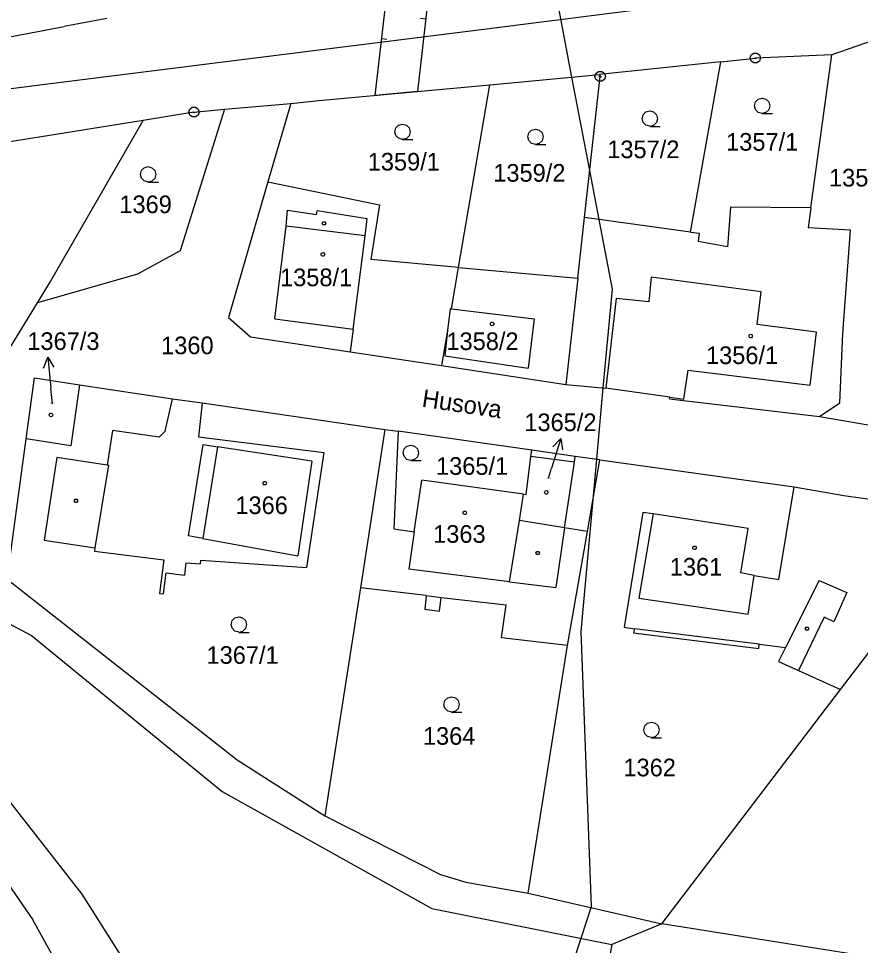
# Model space of a CAD drawing. Extents: x -806774 to -803680, y -1151731 to -1150053.
# Drawn here: x -804756.2 to -804675.1, y -1150604.7 to -1150515.4 of the extents above; entities that cross this region are included whole.
import ezdxf

# ---------------------------------------------------------------- set-up
doc = ezdxf.new("R2010")
doc.units = 0
for name, color, linetype in [('1', 7, 'Continuous'), ('11', 7, 'Continuous'), ('12', 7, 'Continuous'), ('13', 7, 'Continuous'), ('2', 7, 'Continuous'), ('3', 7, 'Continuous'), ('4', 7, 'Continuous'), ('5', 7, 'Continuous'), ('6', 7, 'Continuous'), ('7', 7, 'Continuous'), ('8', 7, 'Continuous')]:
    doc.layers.add(name, color=color, linetype=linetype)

msp = doc.modelspace()

# ---------------------------------------------------------------- linework, layer by layer
at = {"layer": '1'}
for p, q in [((-804747.72, -1150515.43), (-804751.83, -1150516.2)), ((-804763.49, -1150518.4), (-804751.83, -1150516.2)), ((-804671.85, -1150516.86), (-804677.85, -1150518.93)), ((-804688.56, -1150519.6), (-804700.23, -1150520.83)), ((-804691.48, -1150536.01), (-804688.56, -1150519.6)), ((-804688.56, -1150519.6), (-804685.22, -1150519.25)), ((-804677.85, -1150518.93), (-804685.22, -1150519.25)), ((-804679.88, -1150533.68), (-804677.85, -1150518.93)), ((-804710.79, -1150521.81), (-804700.23, -1150520.83)), ((-804701.68, -1150534.6), (-804700.17, -1150521.02)), ((-804700.23, -1150520.83), (-804700.17, -1150521.02)), ((-804727.28, -1150523.34), (-804710.79, -1150521.81)), ((-804713.82, -1150539.42), (-804710.79, -1150521.81)), ((-804736.36, -1150524.18), (-804740.64, -1150537.81)), ((-804739.31, -1150524.46), (-804736.36, -1150524.18)), ((-804736.36, -1150524.18), (-804729.97, -1150523.63)), ((-804729.97, -1150523.63), (-804732.19, -1150531.16)), ((-804729.97, -1150523.63), (-804727.28, -1150523.34)), ((-804739.31, -1150524.46), (-804744.2, -1150525.25)), ((-804744.2, -1150525.25), (-804766.8, -1150528.89)), ((-804753.24, -1150540.95), (-804744.2, -1150525.25)), ((-804732.19, -1150531.16), (-804735.99, -1150544.25)), ((-804732.19, -1150531.16), (-804721.42, -1150533.39)), ((-804721.42, -1150533.39), (-804722.26, -1150538.65)), ((-804687.61, -1150533.6), (-804687.89, -1150537.42)), ((-804679.88, -1150533.68), (-804687.61, -1150533.6)), ((-804679.88, -1150533.68), (-804680.14, -1150535.59)), ((-804702.34, -1150540.46), (-804701.68, -1150534.6)), ((-804691.48, -1150536.01), (-804701.68, -1150534.6)), ((-804676.04, -1150535.83), (-804680.14, -1150535.59)), ((-804691.48, -1150536.01), (-804690.63, -1150536.13)), ((-804690.63, -1150536.13), (-804690.74, -1150536.92)), ((-804676.8, -1150545.77), (-804676.04, -1150535.83)), ((-804687.89, -1150537.42), (-804690.74, -1150536.92)), ((-804740.64, -1150537.81), (-804744.74, -1150540.06)), ((-804713.82, -1150539.42), (-804722.26, -1150538.65)), ((-804744.74, -1150540.06), (-804754.4, -1150542.84)), ((-804714.51, -1150543.42), (-804713.82, -1150539.42)), ((-804713.82, -1150539.42), (-804702.34, -1150540.46)), ((-804754.4, -1150542.84), (-804753.24, -1150540.95)), ((-804702.34, -1150540.46), (-804703.48, -1150550.7)), ((-804758.67, -1150549.81), (-804754.4, -1150542.84)), ((-804714.64, -1150543.4), (-804714.87, -1150545.49)), ((-804714.51, -1150543.42), (-804714.64, -1150543.4)), ((-804735.99, -1150544.25), (-804733.85, -1150546.1)), ((-804714.87, -1150545.49), (-804715.46, -1150548.88)), ((-804733.85, -1150546.1), (-804724.25, -1150547.55)), ((-804677.08, -1150552.48), (-804676.8, -1150545.77)), ((-804724.25, -1150547.55), (-804715.46, -1150548.88)), ((-804715.46, -1150548.88), (-804703.48, -1150550.7)), ((-804755.47, -1150555.94), (-804754.67, -1150550.06)), ((-804754.67, -1150550.06), (-804750.33, -1150550.72)), ((-804750.33, -1150550.72), (-804751.16, -1150556.62)), ((-804750.33, -1150550.72), (-804741.39, -1150552.08)), ((-804703.48, -1150550.7), (-804699.63, -1150551.04)), ((-804693.47, -1150551.91), (-804699.63, -1150551.04)), ((-804742.08, -1150555.2), (-804741.39, -1150552.08)), ((-804741.39, -1150552.08), (-804738.53, -1150552.46)), ((-804738.53, -1150552.46), (-804738.89, -1150555.74)), ((-804738.53, -1150552.46), (-804720.91, -1150555.02)), ((-804693.49, -1150552.09), (-804693.47, -1150551.91)), ((-804693.49, -1150552.09), (-804679.04, -1150553.78)), ((-804679.04, -1150553.78), (-804677.08, -1150552.48)), ((-804679.04, -1150553.78), (-804671.44, -1150555.09)), ((-804747.16, -1150555.14), (-804747.69, -1150558.46)), ((-804742.68, -1150555.76), (-804747.16, -1150555.14)), ((-804742.68, -1150555.76), (-804742.08, -1150555.2)), ((-804720.91, -1150555.02), (-804723.28, -1150570.3)), ((-804720.91, -1150555.02), (-804719.65, -1150555.2)), ((-804719.65, -1150555.2), (-804720.05, -1150564.62)), ((-804706.77, -1150557.03), (-804719.65, -1150555.2)), ((-804757.3, -1150569.44), (-804755.47, -1150555.94)), ((-804751.16, -1150556.62), (-804755.47, -1150555.94)), ((-804738.89, -1150555.74), (-804726.81, -1150557.24)), ((-804726.81, -1150557.24), (-804728.47, -1150568.34)), ((-804706.85, -1150557.64), (-804706.77, -1150557.03)), ((-804702.57, -1150557.62), (-804706.77, -1150557.03)), ((-804752.52, -1150557.74), (-804753.73, -1150565.68)), ((-804747.69, -1150558.46), (-804752.52, -1150557.74)), ((-804707.32, -1150561.31), (-804706.85, -1150557.64)), ((-804700.2, -1150557.94), (-804702.57, -1150557.62)), ((-804701.41, -1150564.85), (-804700.2, -1150557.94)), ((-804700.2, -1150557.94), (-804681.49, -1150560.57)), ((-804718.08, -1150564.9), (-804717.35, -1150559.9)), ((-804707.55, -1150561.25), (-804717.35, -1150559.9)), ((-804682.97, -1150569.49), (-804681.49, -1150560.57)), ((-804681.49, -1150560.57), (-804676.7, -1150561.39)), ((-804707.95, -1150563.81), (-804707.55, -1150561.25)), ((-804707.55, -1150561.25), (-804707.32, -1150561.31)), ((-804676.7, -1150561.39), (-804670.97, -1150562.21)), ((-804696.05, -1150563.02), (-804697.86, -1150574.08)), ((-804695.06, -1150563.17), (-804696.05, -1150563.02)), ((-804685.91, -1150564.57), (-804695.06, -1150563.17)), ((-804703.6, -1150564.5), (-804707.95, -1150563.81)), ((-804720.05, -1150564.62), (-804718.08, -1150564.9)), ((-804701.41, -1150564.85), (-804703.6, -1150564.5)), ((-804703.33, -1150575.86), (-804701.41, -1150564.85)), ((-804686.63, -1150568.85), (-804685.91, -1150564.57)), ((-804753.73, -1150565.68), (-804748.85, -1150566.42)), ((-804748.85, -1150566.42), (-804748.89, -1150566.77)), ((-804748.89, -1150566.77), (-804742.21, -1150567.6)), ((-804742.21, -1150567.6), (-804742.62, -1150570.83)), ((-804740.08, -1150567.87), (-804740.23, -1150569.07)), ((-804740.08, -1150567.87), (-804738.67, -1150567.97)), ((-804738.67, -1150567.97), (-804738.65, -1150567.62)), ((-804738.65, -1150567.62), (-804728.47, -1150568.34)), ((-804742.25, -1150570.88), (-804742, -1150568.85)), ((-804742, -1150568.85), (-804740.23, -1150569.07)), ((-804685.35, -1150569.09), (-804686.63, -1150568.85)), ((-804765.48, -1150569.34), (-804754.97, -1150574.87)), ((-804757.3, -1150569.44), (-804735.14, -1150586.85)), ((-804685.35, -1150569.09), (-804682.97, -1150569.49)), ((-804723.28, -1150570.3), (-804726.69, -1150592.24)), ((-804716.93, -1150571.04), (-804723.28, -1150570.3)), ((-804742.62, -1150570.83), (-804742.25, -1150570.88)), ((-804716.93, -1150571.04), (-804717.08, -1150572.33)), ((-804715.65, -1150572.54), (-804715.49, -1150571.21)), ((-804715.49, -1150571.21), (-804709.22, -1150571.94)), ((-804677.01, -1150580.07), (-804670.08, -1150570.98)), ((-804717.08, -1150572.33), (-804715.65, -1150572.54)), ((-804709.68, -1150575.1), (-804709.22, -1150571.94)), ((-804697.86, -1150574.08), (-804696.86, -1150574.23)), ((-804754.97, -1150574.87), (-804736.59, -1150589.91)), ((-804703.33, -1150575.86), (-804709.68, -1150575.1)), ((-804696.86, -1150574.23), (-804696.95, -1150574.63)), ((-804696.95, -1150574.63), (-804684.89, -1150576.12)), ((-804707.1, -1150599.7), (-804703.33, -1150575.86)), ((-804684.89, -1150576.12), (-804684.84, -1150575.72)), ((-804684.84, -1150575.72), (-804682.31, -1150576.03)), ((-804768.67, -1150576.05), (-804750.12, -1150599.8)), ((-804682.31, -1150576.03), (-804682.98, -1150577.37)), ((-804682.98, -1150577.37), (-804681.05, -1150578.24)), ((-804681.05, -1150578.24), (-804677.01, -1150580.07)), ((-804694.22, -1150602.66), (-804677.01, -1150580.07)), ((-804768.67, -1150582.3), (-804754.83, -1150602.27)), ((-804735.14, -1150586.85), (-804726.69, -1150592.24)), ((-804736.59, -1150589.91), (-804716.38, -1150601.17)), ((-804726.69, -1150592.24), (-804715.56, -1150597.91)), ((-804715.56, -1150597.91), (-804713.12, -1150598.64)), ((-804713.12, -1150598.64), (-804707.1, -1150599.7)), ((-804750.12, -1150599.8), (-804728.74, -1150633.39)), ((-804707.1, -1150599.7), (-804694.22, -1150602.66)), ((-804716.38, -1150601.17), (-804699.05, -1150604.64)), ((-804739.17, -1150630.73), (-804754.83, -1150602.27)), ((-804694.22, -1150602.66), (-804699.05, -1150604.64)), ((-804653.81, -1150609.12), (-804694.22, -1150602.66)), ((-804699.05, -1150604.64), (-804701.95, -1150620.52))]:
    msp.add_line(p, q, dxfattribs=at)
at = {"layer": '11'}
msp.add_lwpolyline([(-804712.5, -1150636), (-804702, -1150604.05), (-804701.03, -1150601.09), (-804701, -1150601), (-804702, -1150574.5), (-804700.81, -1150561.44), (-804700.49, -1150557.9), (-804699.87, -1150551.02), (-804699, -1150541.5), (-804700.28, -1150534.79), (-804701.18, -1150530.07), (-804702.89, -1150521.08), (-804705.23, -1150508.8), (-804707.48, -1150497), (-804708.64, -1150490.89), (-804709.2, -1150487.94), (-804711, -1150478.5), (-804713.95, -1150471.68), (-804723.17, -1150450.35)], dxfattribs=at)
at = {"layer": '12'}
for p, q in [((-804731.53, -1150544.37), (-804730.44, -1150535.43)), ((-804722.82, -1150536.38), (-804730.44, -1150535.43)), ((-804723.97, -1150545.37), (-804722.82, -1150536.38)), ((-804695.25, -1150540.37), (-804695.49, -1150542.73)), ((-804684.65, -1150541.76), (-804695.25, -1150540.37)), ((-804685.06, -1150544.92), (-804684.65, -1150541.76)), ((-804698.62, -1150542.42), (-804699.63, -1150551.04)), ((-804695.49, -1150542.73), (-804698.62, -1150542.42)), ((-804714.64, -1150543.4), (-804714.87, -1150545.49)), ((-804714.51, -1150543.42), (-804714.64, -1150543.4)), ((-804714.51, -1150543.42), (-804706.54, -1150544.38)), ((-804731.53, -1150544.37), (-804723.97, -1150545.37)), ((-804706.54, -1150544.38), (-804707.12, -1150549.13)), ((-804714.87, -1150545.49), (-804715.14, -1150547.92)), ((-804679.32, -1150545.66), (-804685.06, -1150544.92)), ((-804679.93, -1150550.77), (-804679.32, -1150545.66)), ((-804715.14, -1150547.92), (-804707.12, -1150549.13)), ((-804755.47, -1150555.94), (-804754.67, -1150550.06)), ((-804754.67, -1150550.06), (-804750.33, -1150550.72)), ((-804692.11, -1150552.1), (-804691.71, -1150549.33)), ((-804691.71, -1150549.33), (-804679.93, -1150550.77)), ((-804750.33, -1150550.72), (-804751.16, -1150556.62)), ((-804693.47, -1150551.91), (-804699.63, -1150551.04)), ((-804693.47, -1150551.91), (-804692.11, -1150552.1)), ((-804751.16, -1150556.62), (-804755.47, -1150555.94)), ((-804737.03, -1150556.7), (-804738.47, -1150565.53)), ((-804727.95, -1150558.1), (-804737.03, -1150556.7)), ((-804727.95, -1150558.1), (-804729.3, -1150567.19)), ((-804707.32, -1150561.31), (-804706.85, -1150557.64)), ((-804702.65, -1150558.17), (-804706.85, -1150557.64)), ((-804703.6, -1150564.5), (-804702.65, -1150558.17)), ((-804718.08, -1150564.9), (-804717.35, -1150559.9)), ((-804707.55, -1150561.25), (-804717.35, -1150559.9)), ((-804707.95, -1150563.81), (-804707.55, -1150561.25)), ((-804707.95, -1150563.81), (-804707.55, -1150561.25)), ((-804707.55, -1150561.25), (-804707.32, -1150561.31)), ((-804695.06, -1150563.17), (-804696.44, -1150571.27)), ((-804685.91, -1150564.57), (-804695.06, -1150563.17)), ((-804708.9, -1150569.7), (-804707.95, -1150563.81)), ((-804703.6, -1150564.5), (-804707.95, -1150563.81)), ((-804718.08, -1150564.9), (-804718.6, -1150568.49)), ((-804686.63, -1150568.85), (-804685.91, -1150564.57)), ((-804738.47, -1150565.53), (-804729.3, -1150567.19)), ((-804708.9, -1150569.7), (-804718.6, -1150568.49)), ((-804685.35, -1150569.09), (-804686.63, -1150568.85)), ((-804685.91, -1150572.82), (-804685.35, -1150569.09)), ((-804696.44, -1150571.27), (-804685.91, -1150572.82))]:
    msp.add_line(p, q, dxfattribs=at)
at = {"layer": '13'}
for p, q in [((-804721.84, -1150522.84), (-804720.43, -1150510.49)), ((-804716.36, -1150510.04), (-804717.79, -1150522.46)), ((-804716.989, -1150515.504), (-804717.486, -1150515.447)), ((-804721.216, -1150517.375), (-804720.719, -1150517.432)), ((-804717.79, -1150522.46), (-804721.84, -1150522.84))]:
    msp.add_line(p, q, dxfattribs=at)
at = {"layer": '3'}
for points in [[(-804684.56, -1150524.58), (-804684.94, -1150524.48), (-804685.21, -1150524.21), (-804685.31, -1150523.84), (-804685.21, -1150523.47), (-804684.94, -1150523.2), (-804684.57, -1150523.1), (-804684.2, -1150523.2), (-804683.93, -1150523.47), (-804683.83, -1150523.85), (-804683.93, -1150524.23), (-804684.2, -1150524.5), (-804684.58, -1150524.6), (-804683.58, -1150524.6)], [(-804695.38, -1150525.82), (-804695.76, -1150525.72), (-804696.03, -1150525.45), (-804696.13, -1150525.08), (-804696.03, -1150524.71), (-804695.76, -1150524.44), (-804695.39, -1150524.34), (-804695.02, -1150524.44), (-804694.75, -1150524.71), (-804694.65, -1150525.09), (-804694.75, -1150525.47), (-804695.02, -1150525.74), (-804695.4, -1150525.84), (-804694.4, -1150525.84)], [(-804719.21, -1150527.08), (-804719.59, -1150526.98), (-804719.86, -1150526.71), (-804719.96, -1150526.34), (-804719.86, -1150525.97), (-804719.59, -1150525.7), (-804719.22, -1150525.6), (-804718.85, -1150525.7), (-804718.58, -1150525.97), (-804718.48, -1150526.35), (-804718.58, -1150526.73), (-804718.85, -1150527), (-804719.23, -1150527.1), (-804718.23, -1150527.1)], [(-804706.4, -1150527.57), (-804706.78, -1150527.47), (-804707.05, -1150527.2), (-804707.15, -1150526.83), (-804707.05, -1150526.46), (-804706.78, -1150526.19), (-804706.41, -1150526.09), (-804706.04, -1150526.19), (-804705.77, -1150526.46), (-804705.67, -1150526.84), (-804705.77, -1150527.22), (-804706.04, -1150527.49), (-804706.42, -1150527.59), (-804705.42, -1150527.59)], [(-804743.72, -1150531.19), (-804744.1, -1150531.09), (-804744.37, -1150530.82), (-804744.47, -1150530.45), (-804744.37, -1150530.08), (-804744.1, -1150529.81), (-804743.73, -1150529.71), (-804743.36, -1150529.81), (-804743.09, -1150530.08), (-804742.99, -1150530.46), (-804743.09, -1150530.84), (-804743.36, -1150531.11), (-804743.74, -1150531.21), (-804742.74, -1150531.21)], [(-804718.41, -1150558.01), (-804718.79, -1150557.91), (-804719.06, -1150557.64), (-804719.16, -1150557.27), (-804719.06, -1150556.9), (-804718.79, -1150556.63), (-804718.42, -1150556.53), (-804718.05, -1150556.63), (-804717.78, -1150556.9), (-804717.68, -1150557.28), (-804717.78, -1150557.66), (-804718.05, -1150557.93), (-804718.43, -1150558.03), (-804717.43, -1150558.03)], [(-804734.98, -1150574.56), (-804735.36, -1150574.46), (-804735.63, -1150574.19), (-804735.73, -1150573.82), (-804735.63, -1150573.45), (-804735.36, -1150573.18), (-804734.99, -1150573.08), (-804734.62, -1150573.18), (-804734.35, -1150573.45), (-804734.25, -1150573.83), (-804734.35, -1150574.21), (-804734.62, -1150574.48), (-804735, -1150574.58), (-804734, -1150574.58)], [(-804714.48, -1150582.26), (-804714.86, -1150582.16), (-804715.13, -1150581.89), (-804715.23, -1150581.52), (-804715.13, -1150581.15), (-804714.86, -1150580.88), (-804714.49, -1150580.78), (-804714.12, -1150580.88), (-804713.85, -1150581.15), (-804713.75, -1150581.53), (-804713.85, -1150581.91), (-804714.12, -1150582.18), (-804714.5, -1150582.28), (-804713.5, -1150582.28)], [(-804695.23, -1150584.71), (-804695.61, -1150584.61), (-804695.88, -1150584.34), (-804695.98, -1150583.97), (-804695.88, -1150583.6), (-804695.61, -1150583.33), (-804695.24, -1150583.23), (-804694.87, -1150583.33), (-804694.6, -1150583.6), (-804694.5, -1150583.98), (-804694.6, -1150584.36), (-804694.87, -1150584.63), (-804695.25, -1150584.73), (-804694.25, -1150584.73)]]:
    msp.add_lwpolyline(points, dxfattribs=at)
at = {"layer": '4'}
for p, q in [((-804730.44, -1150535.43), (-804730.29, -1150533.9)), ((-804730.29, -1150533.9), (-804727.51, -1150534.31)), ((-804727.51, -1150534.31), (-804727.44, -1150533.95)), ((-804722.63, -1150534.73), (-804727.44, -1150533.95)), ((-804722.82, -1150536.38), (-804722.63, -1150534.73)), ((-804731.53, -1150544.37), (-804730.44, -1150535.43)), ((-804722.82, -1150536.38), (-804730.44, -1150535.43)), ((-804723.97, -1150545.37), (-804722.82, -1150536.38)), ((-804695.25, -1150540.37), (-804695.49, -1150542.73)), ((-804684.65, -1150541.76), (-804695.25, -1150540.37)), ((-804685.06, -1150544.92), (-804684.65, -1150541.76)), ((-804698.62, -1150542.42), (-804699.63, -1150551.04)), ((-804695.49, -1150542.73), (-804698.62, -1150542.42)), ((-804714.51, -1150543.42), (-804706.54, -1150544.38)), ((-804731.53, -1150544.37), (-804723.97, -1150545.37)), ((-804706.54, -1150544.38), (-804707.12, -1150549.13)), ((-804723.97, -1150545.37), (-804724.25, -1150547.55)), ((-804714.87, -1150545.49), (-804715.14, -1150547.92)), ((-804679.32, -1150545.66), (-804685.06, -1150544.92)), ((-804679.93, -1150550.77), (-804679.32, -1150545.66)), ((-804715.14, -1150547.92), (-804707.12, -1150549.13)), ((-804692.11, -1150552.1), (-804691.71, -1150549.33)), ((-804691.71, -1150549.33), (-804679.93, -1150550.77)), ((-804693.47, -1150551.91), (-804692.11, -1150552.1)), ((-804739.85, -1150565.28), (-804738.41, -1150556.49)), ((-804737.03, -1150556.7), (-804738.47, -1150565.53)), ((-804738.41, -1150556.49), (-804737.03, -1150556.7)), ((-804727.95, -1150558.1), (-804737.03, -1150556.7)), ((-804727.95, -1150558.1), (-804729.3, -1150567.19)), ((-804702.65, -1150558.17), (-804706.85, -1150557.64)), ((-804702.65, -1150558.17), (-804702.57, -1150557.62)), ((-804747.55, -1150558.47), (-804748.85, -1150566.42)), ((-804747.55, -1150558.47), (-804747.69, -1150558.46)), ((-804703.6, -1150564.5), (-804702.65, -1150558.17)), ((-804695.06, -1150563.17), (-804696.44, -1150571.27)), ((-804708.9, -1150569.7), (-804707.95, -1150563.81)), ((-804738.47, -1150565.53), (-804739.85, -1150565.28)), ((-804718.08, -1150564.9), (-804718.6, -1150568.49)), ((-804703.6, -1150564.5), (-804704.45, -1150570.25)), ((-804738.47, -1150565.53), (-804729.3, -1150567.19)), ((-804708.9, -1150569.7), (-804718.6, -1150568.49)), ((-804708.9, -1150569.7), (-804704.45, -1150570.25)), ((-804685.91, -1150572.82), (-804685.35, -1150569.09)), ((-804679.08, -1150569.57), (-804682.31, -1150576.03)), ((-804679.08, -1150569.57), (-804676.4, -1150570.73)), ((-804716.93, -1150571.04), (-804715.49, -1150571.21)), ((-804696.44, -1150571.27), (-804685.91, -1150572.82)), ((-804676.4, -1150570.73), (-804677.65, -1150573.57)), ((-804678.6, -1150573.12), (-804681.05, -1150578.24)), ((-804677.65, -1150573.57), (-804678.6, -1150573.12)), ((-804684.84, -1150575.72), (-804696.86, -1150574.23))]:
    msp.add_line(p, q, dxfattribs=at)
at = {"layer": '5'}
for points in [[(-804726.7, -1150535.02), (-804726.61, -1150535.17), (-804726.7, -1150535.32), (-804726.88, -1150535.32), (-804726.97, -1150535.17), (-804726.88, -1150535.02)], [(-804726.9, -1150537.99), (-804726.8, -1150538.01), (-804726.75, -1150538.1), (-804726.73, -1150538.16), (-804726.75, -1150538.25), (-804726.83, -1150538.32), (-804726.9, -1150538.33), (-804726.99, -1150538.3), (-804727.05, -1150538.24), (-804727.07, -1150538.16), (-804727.05, -1150538.07), (-804726.97, -1150538)], [(-804710.58, -1150544.69), (-804710.48, -1150544.71), (-804710.43, -1150544.8), (-804710.41, -1150544.86), (-804710.43, -1150544.95), (-804710.51, -1150545.02), (-804710.58, -1150545.03), (-804710.67, -1150545), (-804710.73, -1150544.94), (-804710.75, -1150544.86), (-804710.73, -1150544.77), (-804710.65, -1150544.7)], [(-804685.67, -1150545.86), (-804685.57, -1150545.88), (-804685.52, -1150545.97), (-804685.5, -1150546.03), (-804685.52, -1150546.12), (-804685.6, -1150546.19), (-804685.67, -1150546.2), (-804685.76, -1150546.17), (-804685.82, -1150546.11), (-804685.84, -1150546.03), (-804685.82, -1150545.94), (-804685.74, -1150545.87)], [(-804753.09, -1150553.46), (-804752.99, -1150553.48), (-804752.94, -1150553.57), (-804752.92, -1150553.63), (-804752.94, -1150553.72), (-804753.02, -1150553.79), (-804753.09, -1150553.8), (-804753.18, -1150553.77), (-804753.24, -1150553.71), (-804753.26, -1150553.63), (-804753.24, -1150553.54), (-804753.16, -1150553.47)], [(-804732.49, -1150560.04), (-804732.39, -1150560.06), (-804732.34, -1150560.15), (-804732.32, -1150560.21), (-804732.34, -1150560.3), (-804732.42, -1150560.37), (-804732.49, -1150560.38), (-804732.58, -1150560.35), (-804732.64, -1150560.29), (-804732.66, -1150560.21), (-804732.64, -1150560.12), (-804732.56, -1150560.05)], [(-804705.37, -1150560.92), (-804705.27, -1150560.94), (-804705.22, -1150561.03), (-804705.2, -1150561.09), (-804705.22, -1150561.18), (-804705.3, -1150561.25), (-804705.37, -1150561.26), (-804705.46, -1150561.23), (-804705.52, -1150561.17), (-804705.54, -1150561.09), (-804705.52, -1150561), (-804705.44, -1150560.93)], [(-804750.59, -1150561.76), (-804750.5, -1150561.91), (-804750.59, -1150562.06), (-804750.77, -1150562.06), (-804750.86, -1150561.91), (-804750.77, -1150561.76)], [(-804713.22, -1150562.89), (-804713.12, -1150562.91), (-804713.07, -1150563), (-804713.05, -1150563.06), (-804713.07, -1150563.15), (-804713.15, -1150563.22), (-804713.22, -1150563.23), (-804713.31, -1150563.2), (-804713.37, -1150563.14), (-804713.39, -1150563.06), (-804713.37, -1150562.97), (-804713.29, -1150562.9)], [(-804706.1, -1150566.79), (-804706.01, -1150566.94), (-804706.1, -1150567.09), (-804706.28, -1150567.09), (-804706.37, -1150566.94), (-804706.28, -1150566.79)], [(-804691.09, -1150566.26), (-804690.99, -1150566.28), (-804690.94, -1150566.37), (-804690.92, -1150566.43), (-804690.94, -1150566.52), (-804691.02, -1150566.59), (-804691.09, -1150566.6), (-804691.18, -1150566.57), (-804691.24, -1150566.51), (-804691.26, -1150566.43), (-804691.24, -1150566.34), (-804691.16, -1150566.27)], [(-804680.16, -1150574.07), (-804680.07, -1150574.22), (-804680.16, -1150574.37), (-804680.34, -1150574.37), (-804680.43, -1150574.22), (-804680.34, -1150574.07)]]:
    msp.add_lwpolyline(points, close=True, dxfattribs=at)
at = {"layer": '6'}
for p, q in [((-804711.9, -1150516.53), (-804689.85, -1150513.74)), ((-804745.47, -1150520.74), (-804711.9, -1150516.53)), ((-804770.86, -1150523.92), (-804745.47, -1150520.74))]:
    msp.add_line(p, q, dxfattribs=at)
at = {"layer": '7'}
for p, q in [((-804753.394, -1150548.074), (-804753.1, -1150551.06)), ((-804752.95, -1150552.55), (-804753.1, -1150551.06)), ((-804703.974, -1150555.901), (-804704.85, -1150558.77)), ((-804705.14, -1150559.73), (-804704.85, -1150558.77))]:
    msp.add_line(p, q, dxfattribs=at)
for points in [[(-804753.793, -1150549.119), (-804753.394, -1150548.074), (-804752.798, -1150549.021)], [(-804704.744, -1150556.711), (-804703.974, -1150555.901), (-804703.788, -1150557.003)]]:
    msp.add_lwpolyline(points, dxfattribs=at)
at = {"layer": '8'}
for p, q in [((-804685.34, -1150519.25), (-804685.1, -1150519.25)), ((-804700.29, -1150521.02), (-804700.05, -1150521.02)), ((-804739.43, -1150524.46), (-804739.19, -1150524.46))]:
    msp.add_line(p, q, dxfattribs=at)
for points in [[(-804685.07, -1150518.77), (-804684.82, -1150518.95), (-804684.72, -1150519.24), (-804684.82, -1150519.53), (-804685.07, -1150519.71), (-804685.38, -1150519.71), (-804685.63, -1150519.53), (-804685.73, -1150519.24), (-804685.63, -1150518.95), (-804685.38, -1150518.77)], [(-804700.02, -1150520.54), (-804699.77, -1150520.72), (-804699.67, -1150521.01), (-804699.77, -1150521.3), (-804700.02, -1150521.48), (-804700.33, -1150521.48), (-804700.58, -1150521.3), (-804700.68, -1150521.01), (-804700.58, -1150520.72), (-804700.33, -1150520.54)], [(-804739.16, -1150523.98), (-804738.91, -1150524.16), (-804738.81, -1150524.45), (-804738.91, -1150524.74), (-804739.16, -1150524.92), (-804739.47, -1150524.92), (-804739.72, -1150524.74), (-804739.82, -1150524.45), (-804739.72, -1150524.16), (-804739.47, -1150523.98)]]:
    msp.add_lwpolyline(points, close=True, dxfattribs=at)

# ---------------------------------------------------------------- texts
at = {"layer": '2'}
for s, height, p in [('1357/1', 1.7, (-804688.04, -1150528.17)), ('1357/2', 1.7, (-804699.492, -1150528.89)), ('1359/1', 1.7, (-804722.57, -1150530.08)), ('1359/2', 1.7, (-804710.472, -1150531.16)), ('1355', 1.7, (-804678.126, -1150531.62)), ('1369', 1.7, (-804746.502, -1150534.19)), ('1358/1', 1.7, (-804731.017, -1150541.23)), ('1358/2', 1.7, (-804714.989, -1150547.38)), ('1360', 1.7, (-804742.479, -1150547.78)), ('1356/1', 1.7, (-804689.98, -1150548.73)), ('1367/3', 0.1, (-804753.18, -1150552.55)), ('1365/1', 1.7, (-804715.99, -1150559.4)), ('1365/2', 0.1, (-804705.374, -1150559.73)), ('1366', 1.7, (-804735.322, -1150563.18)), ('1363', 1.7, (-804716.269, -1150565.95)), ('1361', 1.7, (-804693.464, -1150569.11)), ('1367/1', 1.7, (-804738.103, -1150577.61)), ('1364', 1.7, (-804717.252, -1150585.41)), ('1362', 1.7, (-804697.936, -1150588.45))]:
    msp.add_text(s, height=height, dxfattribs=at).set_placement(p)
at = {"layer": '7'}
for s, p in [('1367/3', (-804755.368, -1150547.37)), ('1365/2', (-804707.482, -1150555.19))]:
    msp.add_text(s, height=1.7, dxfattribs=at).set_placement(p)
msp.add_text('Husova', height=1.7, rotation=351.5669, dxfattribs=at).set_placement((-804717.417, -1150552.832))

doc.saveas('drawing.dxf')
